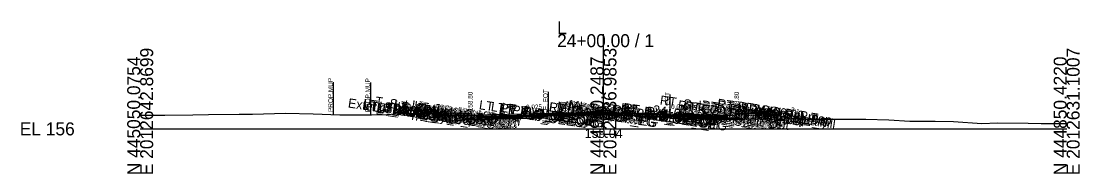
# Model space of a CAD drawing. Extents: x -26 to 4203, y -10 to 9526.
# Drawn here: x 974.3 to 1202.8, y 3990.3 to 4023.2 of the extents above; entities that cross this region are included whole.
import ezdxf

# ---------------------------------------------------------------- set-up
doc = ezdxf.new("R2010")
doc.units = 0
for name, color, linetype in [('Default', 7, 'Continuous'), ('Exist CMT Pavement', 7, 'Continuous'), ('Exist Cross Section Cell', 7, 'Continuous'), ('Exist XS Center Line Elevation Label', 7, 'Continuous'), ('Exist XS Ground Line', 7, 'Continuous'), ('Prop CMT Conc Surface', 7, 'Continuous'), ('Prop CMT Concrete Structures', 7, 'Continuous'), ('Prop CMT Pvmt Course 1', 7, 'Continuous'), ('Prop CMT Pvmt Course 1 CG', 7, 'Continuous'), ('Prop CMT Pvmt Course 1 Wedge', 7, 'Continuous'), ('Prop CMT Pvmt Course 2', 7, 'Continuous'), ('Prop CMT Pvmt Course 2 Wedge', 7, 'Continuous'), ('Prop CMT Pvmt Course 3', 7, 'Continuous'), ('Prop CMT Pvmt Course 3 Wedge', 7, 'Continuous'), ('Prop CMT Pvmt Surface', 7, 'Continuous'), ('Prop CMT Pvmt Wedge Surface 1', 7, 'Continuous'), ('Prop CMT Pvmt Wedge Surface 2', 7, 'Continuous'), ('Prop CMT Pvmt Wedge Surface 3', 7, 'Continuous'), ('Prop CMT Slope Grass', 7, 'Continuous'), ('Prop CMT Subgrade Earthwork', 7, 'Continuous'), ('Prop XS Hydro Elevations', 7, 'Continuous'), ('Prop XS Label Text', 7, 'Continuous'), ('Prop XS SE Text', 7, 'Continuous'), ('Prop XS Side Slope Text', 7, 'Continuous'), ('Scratch_Level_0', 7, 'Continuous')]:
    doc.layers.add(name, color=color, linetype=linetype)

msp = doc.modelspace()

# ---------------------------------------------------------------- linework, layer by layer
at = {"layer": 'Exist CMT Pavement'}
for points in [[(1100, 4003.04), (1099.24, 4003.05), (1097.9, 4003.05), (1097.71, 4003.06), (1097.6, 4003.06), (1095.19, 4003.06), (1093.08, 4003.06), (1092.7, 4003.06), (1090.67, 4003.03), (1090.16, 4003.02), (1088.31, 4003.01), (1088.08, 4003.01)], [(1100, 4003.04), (1100.14, 4003.04), (1100.18, 4003.04), (1100.23, 4003.04), (1102.04, 4003.05), (1102.61, 4003.04), (1102.7, 4003.04), (1102.9, 4003.03), (1105.19, 4002.91), (1107.21, 4002.83), (1107.67, 4002.82), (1108.2, 4002.78), (1110.2, 4002.65), (1110.89, 4002.62), (1112.72, 4002.52), (1113.75, 4002.44), (1114.36, 4002.4), (1114.37, 4002.4)]]:
    msp.add_lwpolyline(points, dxfattribs=at)
at = {"layer": 'Exist Cross Section Cell'}
for p, q in [((1100, 4000), (1100, 4020.42)), ((1000, 4000), (1100, 4000)), ((1100, 4000), (1200, 4000))]:
    msp.add_line(p, q, dxfattribs=at)
at = {"layer": 'Exist XS Ground Line'}
msp.add_lwpolyline([(1000, 4002.95), (1001.32, 4002.97), (1005.3, 4002.97), (1011.34, 4003.03), (1014.76, 4003.09), (1021.36, 4003.18), (1024.22, 4003.19), (1031.38, 4003.36), (1037.32, 4003.22), (1043.13, 4003.01), (1044.86, 4003.01), (1049.9, 4003.01), (1053.22, 4003.12), (1054.19, 4003.18), (1057.03, 4003.35), (1057.45, 4003.38), (1060.23, 4003.29), (1064.42, 4003.07), (1067.31, 4002.98), (1069.5, 4002.99), (1070.53, 4002.95), (1071.56, 4002.89), (1071.92, 4002.9), (1072.32, 4002.8), (1076.37, 4002.35), (1077.97, 4002.3), (1083.3, 4002.73), (1085.65, 4002.93), (1087.69, 4003.01), (1088.07, 4003.01), (1090.16, 4003.02), (1090.67, 4003.03), (1092.7, 4003.06), (1093.08, 4003.06), (1095.19, 4003.06), (1097.9, 4003.05), (1099.24, 4003.05), (1100.23, 4003.04), (1102.04, 4003.05), (1102.9, 4003.03), (1105.19, 4002.91), (1107.21, 4002.83), (1107.67, 4002.82), (1108.2, 4002.78), (1110.2, 4002.65), (1110.89, 4002.62), (1112.72, 4002.52), (1113.75, 4002.44), (1114.36, 4002.4), (1116.78, 4002.14), (1118.32, 4001.96), (1119, 4002.04), (1122.69, 4002.4), (1129.09, 4002.17), (1132.38, 4002.17), (1143.6, 4002.1), (1151.6, 4002.12), (1156.67, 4002.06), (1161.62, 4001.96), (1166.13, 4001.65), (1171.64, 4001.63), (1175.6, 4001.59), (1181.65, 4001.19), (1185.06, 4001.32), (1191.67, 4001.23), (1194.52, 4001.18), (1200, 4001.18)], dxfattribs=at)
at = {"layer": 'Prop CMT Conc Surface'}
for points in [[(1071.25, 4002.8), (1071.25, 4003.3), (1070.75, 4003.3)], [(1073.25, 4002.93), (1071.25, 4002.8)], [(1126.75, 4002.93), (1128.75, 4002.8)], [(1128.75, 4002.8), (1128.75, 4003.3), (1129.25, 4003.3)], [(1133.25, 4003.39), (1138.25, 4003.49)]]:
    msp.add_lwpolyline(points, dxfattribs=at)
at = {"layer": 'Prop CMT Concrete Structures'}
for points in [[(1102, 4003.55), (1101.99, 4003.71), (1101.24, 4003.96), (1100, 4003.99), (1098.76, 4003.96), (1098.01, 4003.71), (1098, 4003.55)], [(1073.25, 4002.93), (1071.25, 4002.8), (1071.25, 4003.3), (1070.75, 4003.3)], [(1070.75, 4003.3), (1070.75, 4002.28), (1073.25, 4002.35)], [(1073.25, 4002.35), (1073.25, 4002.93)], [(1098, 4003.55), (1100, 4003.6), (1102, 4003.55)], [(1126.75, 4002.93), (1128.75, 4002.8), (1128.75, 4003.3), (1129.25, 4003.3)], [(1129.25, 4003.3), (1129.25, 4002.28), (1126.75, 4002.35)], [(1126.75, 4002.35), (1126.75, 4002.93)], [(1138.25, 4003.49), (1133.25, 4003.39)], [(1133.25, 4003.39), (1133.25, 4003.06)], [(1133.25, 4003.06), (1138.25, 4003.16)], [(1138.25, 4003.16), (1138.25, 4003.49)]]:
    msp.add_lwpolyline(points, dxfattribs=at)
at = {"layer": 'Prop CMT Pvmt Course 1'}
for points in [[(1100, 4003.6), (1073.25, 4002.93)], [(1073.25, 4002.68), (1088.08, 4003.05)], [(1073.25, 4002.93), (1073.25, 4002.68)], [(1088.08, 4003.17), (1100, 4003.47)], [(1088.08, 4003.05), (1088.08, 4003.17)], [(1100, 4003.35), (1100, 4003.6)], [(1100, 4003.6), (1126.75, 4002.93)], [(1100, 4003.35), (1100, 4003.6)], [(1100, 4003.47), (1100, 4003.35), (1100, 4003.35)], [(1114.37, 4003.11), (1100, 4003.47)], [(1100, 4003.47), (1100, 4003.35), (1100, 4003.35)], [(1114.37, 4002.99), (1114.37, 4003.11)], [(1126.75, 4002.68), (1114.37, 4002.99)], [(1126.75, 4002.93), (1126.75, 4002.68)]]:
    msp.add_lwpolyline(points, dxfattribs=at)
at = {"layer": 'Prop CMT Pvmt Course 1 CG'}
for points in [[(1073.25, 4002.35), (1070.25, 4002.27), (1069.91, 4001.93)], [(1069.91, 4001.93), (1073.25, 4002.01)], [(1073.25, 4002.01), (1073.25, 4002.35)], [(1126.75, 4002.35), (1129.75, 4002.27), (1130.09, 4001.93)], [(1126.75, 4002.01), (1126.75, 4002.35)], [(1130.09, 4001.93), (1126.75, 4002.01)]]:
    msp.add_lwpolyline(points, dxfattribs=at)
at = {"layer": 'Prop CMT Pvmt Course 1 Wedge'}
for points in [[(1088.08, 4003.17), (1088.31, 4003.18), (1090.16, 4003.23), (1090.67, 4003.24), (1092.7, 4003.29), (1093.08, 4003.3), (1095.19, 4003.35), (1097.6, 4003.41), (1097.71, 4003.42), (1097.9, 4003.42), (1099.24, 4003.45), (1100, 4003.47)], [(1100, 4003.35), (1099.24, 4003.33), (1097.9, 4003.3), (1097.71, 4003.29), (1097.6, 4003.29), (1095.19, 4003.23), (1093.08, 4003.18), (1092.7, 4003.17), (1090.67, 4003.12), (1090.16, 4003.1), (1088.31, 4003.06), (1088.08, 4003.05)], [(1088.08, 4003.05), (1088.08, 4003.17)], [(1100, 4003.47), (1100, 4003.35)], [(1100, 4003.47), (1100.14, 4003.47), (1100.18, 4003.47), (1100.23, 4003.47), (1102.04, 4003.42), (1102.61, 4003.41), (1102.7, 4003.41), (1102.9, 4003.4), (1105.19, 4003.34), (1107.21, 4003.29), (1107.67, 4003.28), (1108.2, 4003.27), (1110.2, 4003.22), (1110.89, 4003.2), (1112.72, 4003.16), (1113.75, 4003.13), (1114.36, 4003.11), (1114.37, 4003.11)], [(1100, 4003.35), (1100, 4003.47)], [(1114.37, 4002.99), (1114.36, 4002.99), (1113.75, 4003), (1112.72, 4003.03), (1110.89, 4003.08), (1110.2, 4003.09), (1108.2, 4003.14), (1107.67, 4003.16), (1107.21, 4003.17), (1105.19, 4003.22), (1102.9, 4003.28), (1102.7, 4003.28), (1102.61, 4003.28), (1102.04, 4003.3), (1100.23, 4003.34), (1100.18, 4003.34), (1100.14, 4003.35), (1100, 4003.35)], [(1114.37, 4003.11), (1114.37, 4002.99)]]:
    msp.add_lwpolyline(points, dxfattribs=at)
at = {"layer": 'Prop CMT Pvmt Course 2'}
for points in [[(1088.08, 4003.05), (1073.25, 4002.68)], [(1073.25, 4002.35), (1088.08, 4002.72)], [(1073.25, 4002.68), (1073.25, 4002.35)], [(1088.08, 4002.72), (1088.08, 4003.05)], [(1114.37, 4002.66), (1114.37, 4002.99)], [(1114.37, 4002.99), (1126.75, 4002.68)], [(1126.75, 4002.35), (1114.37, 4002.66)], [(1126.75, 4002.68), (1126.75, 4002.35)]]:
    msp.add_lwpolyline(points, dxfattribs=at)
at = {"layer": 'Prop CMT Pvmt Course 2 Wedge'}
for points in [[(1088.08, 4003.05), (1088.31, 4003.06), (1090.16, 4003.1), (1090.67, 4003.12), (1092.7, 4003.17), (1093.08, 4003.18), (1095.19, 4003.23), (1097.6, 4003.29), (1097.71, 4003.29), (1097.9, 4003.3), (1099.24, 4003.33), (1100, 4003.35)], [(1100, 4003.04), (1099.24, 4003.05), (1097.9, 4003.05), (1097.71, 4003.06), (1097.6, 4003.06), (1095.19, 4003.06), (1093.08, 4003.06), (1092.7, 4003.06), (1090.67, 4003.03), (1090.16, 4003.02), (1088.31, 4003.01), (1088.08, 4003.01)], [(1088.08, 4003.01), (1088.08, 4003.05)], [(1100, 4003.35), (1100.14, 4003.35), (1100.18, 4003.34), (1100.23, 4003.34), (1102.04, 4003.3), (1102.61, 4003.28), (1102.7, 4003.28), (1102.9, 4003.28), (1105.19, 4003.22), (1107.21, 4003.17), (1107.67, 4003.16), (1108.2, 4003.14), (1110.2, 4003.09), (1110.89, 4003.08), (1112.72, 4003.03), (1113.75, 4003), (1114.36, 4002.99), (1114.37, 4002.99)], [(1100, 4003.04), (1100, 4003.35)], [(1100, 4003.35), (1100, 4003.04)], [(1114.37, 4002.66), (1114.36, 4002.66), (1113.75, 4002.67), (1112.72, 4002.7), (1110.89, 4002.74), (1110.2, 4002.76), (1108.2, 4002.81), (1107.67, 4002.82), (1107.21, 4002.83), (1107.14, 4002.84), (1105.19, 4002.91), (1102.9, 4003.03), (1102.7, 4003.04), (1102.61, 4003.04), (1102.04, 4003.05), (1100.23, 4003.04), (1100.18, 4003.04), (1100.14, 4003.04), (1100, 4003.04)], [(1114.37, 4002.99), (1114.37, 4002.66)]]:
    msp.add_lwpolyline(points, dxfattribs=at)
at = {"layer": 'Prop CMT Pvmt Course 3'}
for points in [[(1088.08, 4002.72), (1073.25, 4002.35)], [(1073.25, 4002.01), (1088.08, 4002.38)], [(1073.25, 4002.35), (1073.25, 4002.01)], [(1088.08, 4002.38), (1088.08, 4002.72)], [(1114.37, 4002.66), (1126.75, 4002.35)], [(1114.37, 4002.32), (1114.37, 4002.66)], [(1126.75, 4002.01), (1114.37, 4002.32)], [(1126.75, 4002.35), (1126.75, 4002.01)]]:
    msp.add_lwpolyline(points, dxfattribs=at)
at = {"layer": 'Prop CMT Pvmt Course 3 Wedge'}
for points in [[(1114.37, 4002.4), (1114.36, 4002.4), (1113.75, 4002.44), (1112.72, 4002.52), (1110.89, 4002.62), (1110.2, 4002.65), (1108.2, 4002.78), (1107.67, 4002.82), (1107.21, 4002.83), (1107.15, 4002.84)], [(1107.15, 4002.84), (1107.21, 4002.83)], [(1107.21, 4002.83), (1107.67, 4002.82), (1108.2, 4002.81), (1110.2, 4002.76), (1110.89, 4002.74), (1112.72, 4002.7), (1113.75, 4002.67), (1114.36, 4002.66), (1114.37, 4002.66)], [(1114.37, 4002.66), (1114.37, 4002.4)]]:
    msp.add_lwpolyline(points, dxfattribs=at)
at = {"layer": 'Prop CMT Pvmt Surface'}
for points in [[(1100, 4003.6), (1073.25, 4002.93)], [(1100, 4003.6), (1126.75, 4002.93)]]:
    msp.add_lwpolyline(points, dxfattribs=at)
at = {"layer": 'Prop CMT Pvmt Wedge Surface 1'}
for points in [[(1088.08, 4003.05), (1073.25, 4002.68)], [(1073.25, 4002.68), (1073.25, 4002.93)], [(1100, 4003.47), (1088.08, 4003.17)], [(1088.08, 4003.17), (1088.08, 4003.05)], [(1100, 4003.47), (1114.37, 4003.11)], [(1114.37, 4003.11), (1114.37, 4002.99)], [(1114.37, 4002.99), (1126.75, 4002.68)], [(1126.75, 4002.68), (1126.75, 4002.93)]]:
    msp.add_lwpolyline(points, dxfattribs=at)
at = {"layer": 'Prop CMT Pvmt Wedge Surface 2'}
for points in [[(1100, 4003.35), (1073.25, 4002.68)], [(1073.25, 4002.68), (1073.25, 4002.93)], [(1100, 4003.35), (1126.75, 4002.68)], [(1126.75, 4002.68), (1126.75, 4002.93)]]:
    msp.add_lwpolyline(points, dxfattribs=at)
at = {"layer": 'Prop CMT Pvmt Wedge Surface 3'}
for points in [[(1100, 4003.01), (1073.25, 4002.35)], [(1073.25, 4002.35), (1073.25, 4002.93)], [(1100, 4003.01), (1126.75, 4002.35)], [(1126.75, 4002.35), (1126.75, 4002.93)]]:
    msp.add_lwpolyline(points, dxfattribs=at)
at = {"layer": 'Prop CMT Slope Grass'}
for points in [[(1070.75, 4003.3), (1061.25, 4003.49), (1060.59, 4003.27)], [(1129.25, 4003.3), (1138.75, 4003.49), (1142.9, 4002.11)]]:
    msp.add_lwpolyline(points, dxfattribs=at)
at = {"layer": 'Prop CMT Subgrade Earthwork'}
for points in [[(1073.25, 4002.01), (1069.91, 4001.93), (1068.49, 4003.34)], [(1088.08, 4002.38), (1073.25, 4002.01)], [(1088.08, 4002.38), (1088.09, 4003.01)], [(1114.37, 4002.32), (1114.35, 4002.4)], [(1114.37, 4002.32), (1126.75, 4002.01)], [(1126.75, 4002.01), (1130.09, 4001.93), (1131.51, 4003.34)]]:
    msp.add_lwpolyline(points, dxfattribs=at)
at = {"layer": 'Prop XS Label Text'}
for p, q in [((1041.68, 4010.07), (1041.68, 4003.07)), ((1049.73, 4010.01), (1049.73, 4003.01)), ((1088.07, 4008.01), (1088.07, 4003.01)), ((1114.36, 4007.4), (1114.36, 4002.4))]:
    msp.add_line(p, q, dxfattribs=at)

# ---------------------------------------------------------------- texts
at = {"layer": 'Default'}
msp.add_text('-', height=0.0001, dxfattribs=at).set_placement((1000, 4000))
at = {"layer": 'Exist Cross Section Cell'}
for s, p in [('L', (1090, 4020.42)), ('24+00.00 / 1', (1090, 4017.62)), ('EL 156', (974, 3998.6))]:
    msp.add_text(s, height=2.8, dxfattribs=at).set_placement(p)
for s, p in [('N 445050.0754', (1000, 3990)), ('E 2012642.8699', (1002.8, 3990)), ('N 444950.2487', (1100, 3990)), ('E 2012636.9853', (1102.8, 3990)), ('N 444850.4220', (1200, 3990)), ('E 2012631.1007', (1202.8, 3990))]:
    msp.add_text(s, height=2.8, rotation=90, dxfattribs=at).set_placement(p)
at = {"layer": 'Exist XS Center Line Elevation Label'}
msp.add_text('159.04', height=2, dxfattribs=at).set_placement((1095.96, 3998.04))
at = {"layer": 'Prop XS Hydro Elevations'}
for p in [(1071.75, 4003.8), (1129.25, 4003.8)]:
    msp.add_text('158.80', height=1, rotation=90, dxfattribs=at).set_placement(p)
at = {"layer": 'Prop XS Label Text'}
for s, p in [('PROP.MUP', (1041.58, 4003.64)), ('PROP.MUP', (1049.63, 4003.58)), ('E. EOT', (1087.97, 4004.03)), ('E. EOT', (1114.26, 4003.42))]:
    msp.add_text(s, height=1, rotation=90, dxfattribs=at).set_placement(p)
at = {"layer": 'Prop XS SE Text'}
for rotation, p in [(1.4327, (1083.3, 4004.19)), (358.5674, (1114.59, 4004.31))]:
    msp.add_text('0.025', height=1, rotation=rotation, dxfattribs=at).set_placement(p)
at = {"layer": 'Prop XS Side Slope Text'}
for rotation, p in [(18.4829, (1059.93, 4003.84)), (341.57, (1140.31, 4003.76))]:
    msp.add_text('3:1', height=1, rotation=rotation, dxfattribs=at).set_placement(p)
at = {"layer": 'Scratch_Level_0'}
for s, p in [('Exterior Boundary', (1044.76, 4004.63)), ('LT_SDWK_Out_Top', (1047.99, 4004.54)), ('LT_Sub_Trench_Out_DLT', (1049.13, 4005.24)), ('LT_PV_Sub_Tie_Out', (1073.05, 4004.25)), ('MI_Top Out', (1092.42, 4004.28)), ('RT_Sub_Trench_Out_DLT', (1112.09, 4005.25)), ('RT_SDWK_Out_Top', (1124.44, 4004.55)), ('LT_SDWK_Out_Bot', (1048.02, 4004.21)), ('LT_Slope_Cut', (1050.19, 4003.82)), ('LT_Slope_Fill', (1051.06, 4003.69)), ('LT_CSLP_Pnt', (1051.38, 4003.96)), ('24+00.00', (1054.65, 4003.51)), ('LT_SDWK_In_Top', (1054.59, 4004.2)), ('LT_SDWK_In_Bot', (1054.63, 4003.86)), ('LT_CG1_Shelf_Out', (1056.8, 4003.28)), ('LT_CG_Top_Face', (1058.5, 4004.2)), ('LT_CG_Top_BOC', (1059.01, 4004.05)), ('24+00.00', (1059.13, 4003.43)), ('LT_CG_Bot_BOC', (1059.05, 4003.03)), ('LT_CG_Top_Gut', (1059.47, 4003.56)), ('24+00.00', (1059.96, 4003.41)), ('LT_Sub_OEOP', (1059.98, 4002.41)), ('24+00.00', (1062.79, 4003.35)), ('LT_CG_Bot_IE', (1063.13, 4002.85)), ('LT_Sub_OEOT', (1063.29, 4002.5)), ('LT_PV2_OEOT', (1063.38, 4003.15)), ('LT_PV3_OEOT', (1063.38, 4002.82)), ('LT_PV1_OEOT', (1063.94, 4003.31)), ('24+00.00', (1064.14, 4003.32)), ('LT_PV_OEEOP_EG', (1075.61, 4003.87)), ('LT_Sub_OEEOP', (1077.26, 4003)), ('LT_PV2_OEEOP', (1077.35, 4003.65)), ('LT_PV3_OEEOP', (1077.35, 4003.31)), ('LT_PV1_OEEOP', (1077.91, 4003.69)), ('RT_PV_IEEOP_EG', (1088.12, 4003.81)), ('LT_PV_IEEOP_EG', (1088.17, 4003.81)), ('MI_Face In', (1089.84, 4003.93)), ('RT_PV2_IEEOP', (1089.87, 4003.86)), ('RT_PV3_IEEOP', (1089.87, 4003.52)), ('LT_PV2_IEEOP', (1089.92, 4003.85)), ('LT_PV3_IEEOP', (1089.92, 4003.52)), ('RT_PV1_IEEOP', (1090.43, 4003.9)), ('LT_PV1_IEEOP', (1090.48, 4003.89)), ('MI_Bot In', (1090.81, 4003.62)), ('MI_Top In', (1091.54, 4004.04)), ('MI_Face Out', (1092.22, 4004.17)), ('MI_Crown', (1093, 4004.03)), ('MI_Bot Out', (1093.21, 4003.86)), ('PV2_PGL', (1093.82, 4003.26)), ('PV1_PGL', (1094.38, 4003.43)), ('24+00.00', (1095.09, 4003.67)), ('MI_Bot', (1095.09, 4003.32)), ('RT_PV_Sub_Tie_Out', (1099.27, 4003.65)), ('RT_PV_OEEOP_EG', (1101.85, 4003.26)), ('RT_Sub_OEEOP', (1103.51, 4002.94)), ('RT_PV2_OEEOP', (1103.6, 4003.59)), ('RT_PV3_OEEOP', (1103.6, 4003.26)), ('RT_PV1_OEEOP', (1104.16, 4003.63)), ('24+00.00', (1110.54, 4003.19)), ('RT_CG_Top_Face', (1115.96, 4004.21)), ('RT_CG1_Shelf_Out', (1116.26, 4003.28)), ('RT_CG_Bot_IE', (1116.58, 4002.86)), ('RT_Sub_OEOT', (1116.74, 4002.5)), ('RT_PV2_OEOT', (1116.84, 4003.16)), ('RT_PV3_OEOT', (1116.84, 4002.82)), ('RT_CG_Top_Gut', (1116.92, 4003.56)), ('RT_PV1_OEOT', (1117.4, 4003.32)), ('RT_CG_Top_BOC', (1117.47, 4004.06)), ('RT_CG_Bot_BOC', (1117.5, 4003.04)), ('RT_Sub_OEOP', (1120.12, 4002.42)), ('24+00.00', (1120.49, 4002.91)), ('RT_SDWK_In_Top', (1121.05, 4004.21)), ('RT_SDWK_In_Bot', (1121.08, 4003.87)), ('24+00.00', (1121.84, 4003.06)), ('RT_SDWK_Out_Bot', (1124.47, 4004.21)), ('24+00.00', (1125.42, 4003.39)), ('Exterior Boundary', (1127.07, 4003.47)), ('24+00.00', (1128.24, 4003.45)), ('RT_CSLP_Pnt', (1128.84, 4003.97)), ('24+00.00', (1132, 4003.46)), ('RT_Slope_Fill', (1133.33, 4002.53))]:
    msp.add_text(s, height=2, rotation=351.4697, dxfattribs=at).set_placement(p)

doc.saveas('drawing.dxf')
